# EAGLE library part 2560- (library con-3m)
3M (TM) Pak 100 4-Wall Header Source: 3M
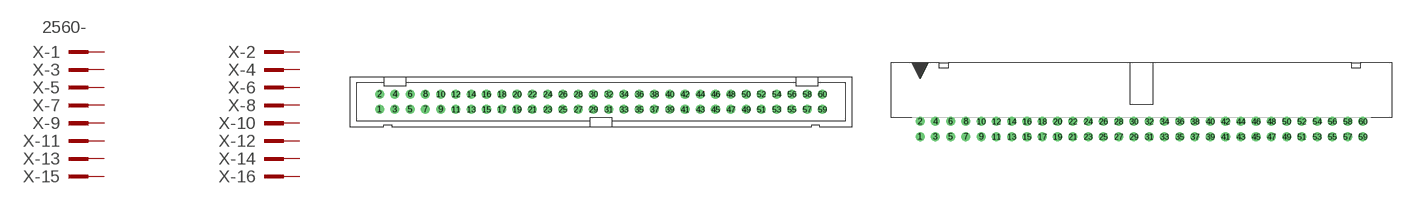
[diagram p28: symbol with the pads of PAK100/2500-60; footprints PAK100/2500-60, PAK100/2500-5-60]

Designator prefix X; gates -1=PINV -2=PIN -3=PIN -4=PIN -5=PIN -6=PIN -7=PIN -8=PIN -9=PIN -10=PIN -11=PIN -12=PIN -13=PIN -14=PIN -15=PIN -16=PIN -17=PIN -18=PIN -19=PIN -20=PIN -21=PIN -22=PIN -23=PIN -24=PIN -25=PIN -26=PIN -27=PIN -28=PIN -29=PIN -30=PIN -31=PIN -32=PIN -33=PIN -34=PIN -35=PIN -36=PIN -37=PIN -38=PIN -39=PIN -40=PIN -41=PIN -42=PIN -43=PIN -44=PIN -45=PIN -46=PIN -47=PIN -48=PIN -49=PIN -50=PIN -51=PIN -52=PIN -53=PIN -54=PIN -55=PIN -56=PIN -57=PIN -58=PIN -59=PIN -60=PIN

## 2560- (OC_FARNELL: unknown; OC_NEWARK: unknown)  [PAK100/2500-60]
1  -1:KL  pas
2  -2:KL  pas
3  -3:KL  pas
4  -4:KL  pas
5  -5:KL  pas
6  -6:KL  pas
7  -7:KL  pas
8  -8:KL  pas
9  -9:KL  pas
10  -10:KL  pas
11  -11:KL  pas
12  -12:KL  pas
13  -13:KL  pas
14  -14:KL  pas
15  -15:KL  pas
16  -16:KL  pas
17  -17:KL  pas
18  -18:KL  pas
19  -19:KL  pas
20  -20:KL  pas
21  -21:KL  pas
22  -22:KL  pas
23  -23:KL  pas
24  -24:KL  pas
25  -25:KL  pas
26  -26:KL  pas
27  -27:KL  pas
28  -28:KL  pas
29  -29:KL  pas
30  -30:KL  pas
31  -31:KL  pas
32  -32:KL  pas
33  -33:KL  pas
34  -34:KL  pas
35  -35:KL  pas
36  -36:KL  pas
37  -37:KL  pas
38  -38:KL  pas
39  -39:KL  pas
40  -40:KL  pas
41  -41:KL  pas
42  -42:KL  pas
43  -43:KL  pas
44  -44:KL  pas
45  -45:KL  pas
46  -46:KL  pas
47  -47:KL  pas
48  -48:KL  pas
49  -49:KL  pas
50  -50:KL  pas
51  -51:KL  pas
52  -52:KL  pas
53  -53:KL  pas
54  -54:KL  pas
55  -55:KL  pas
56  -56:KL  pas
57  -57:KL  pas
58  -58:KL  pas
59  -59:KL  pas
60  -60:KL  pas

## 2560-5 (OC_FARNELL: unknown; OC_NEWARK: unknown)  [PAK100/2500-5-60]
Pads as for PAK100/2500-60

## Footprint PAK100/2500-60 (pad centres in mm)
3M (TM) Pak 100 4-Wall Header Straight Source: 3M
drill 1 pad 1.422 round: 1 -36.83,-1.27; 2 -36.83,1.27; 3 -34.29,-1.27; 4 -34.29,1.27; 5 -31.75,-1.27; 6 -31.75,1.27; 7 -29.21,-1.27; 8 -29.21,1.27; 9 -26.67,-1.27; 10 -26.67,1.27; 11 -24.13,-1.27; 12 -24.13,1.27; 13 -21.59,-1.27; 14 -21.59,1.27; 15 -19.05,-1.27; 16 -19.05,1.27; 17 -16.51,-1.27; 18 -16.51,1.27; 19 -13.97,-1.27; 20 -13.97,1.27; 21 -11.43,-1.27; 22 -11.43,1.27; 23 -8.89,-1.27; 24 -8.89,1.27; 25 -6.35,-1.27; 26 -6.35,1.27; 27 -3.81,-1.27; 28 -3.81,1.27; 29 -1.27,-1.27; 30 -1.27,1.27; 31 1.27,-1.27; 32 1.27,1.27; 33 3.81,-1.27; 34 3.81,1.27; 35 6.35,-1.27; 36 6.35,1.27; 37 8.89,-1.27; 38 8.89,1.27; 39 11.43,-1.27; 40 11.43,1.27; 41 13.97,-1.27; 42 13.97,1.27; 43 16.51,-1.27; 44 16.51,1.27; 45 19.05,-1.27; 46 19.05,1.27; 47 21.59,-1.27; 48 21.59,1.27; 49 24.13,-1.27; 50 24.13,1.27; 51 26.67,-1.27; 52 26.67,1.27; 53 29.21,-1.27; 54 29.21,1.27; 55 31.75,-1.27; 56 31.75,1.27; 57 34.29,-1.27; 58 34.29,1.27; 59 36.83,-1.27; 60 36.83,1.27

## Footprint PAK100/2500-5-60 (pad centres in mm)
3M (TM) Pak 100 4-Wall Header Right Angle Source: 3M
drill 1 pad 1.422 round: 1 -36.83,-1.27; 2 -36.83,1.27; 3 -34.29,-1.27; 4 -34.29,1.27; 5 -31.75,-1.27; 6 -31.75,1.27; 7 -29.21,-1.27; 8 -29.21,1.27; 9 -26.67,-1.27; 10 -26.67,1.27; 11 -24.13,-1.27; 12 -24.13,1.27; 13 -21.59,-1.27; 14 -21.59,1.27; 15 -19.05,-1.27; 16 -19.05,1.27; 17 -16.51,-1.27; 18 -16.51,1.27; 19 -13.97,-1.27; 20 -13.97,1.27; 21 -11.43,-1.27; 22 -11.43,1.27; 23 -8.89,-1.27; 24 -8.89,1.27; 25 -6.35,-1.27; 26 -6.35,1.27; 27 -3.81,-1.27; 28 -3.81,1.27; 29 -1.27,-1.27; 30 -1.27,1.27; 31 1.27,-1.27; 32 1.27,1.27; 33 3.81,-1.27; 34 3.81,1.27; 35 6.35,-1.27; 36 6.35,1.27; 37 8.89,-1.27; 38 8.89,1.27; 39 11.43,-1.27; 40 11.43,1.27; 41 13.97,-1.27; 42 13.97,1.27; 43 16.51,-1.27; 44 16.51,1.27; 45 19.05,-1.27; 46 19.05,1.27; 47 21.59,-1.27; 48 21.59,1.27; 49 24.13,-1.27; 50 24.13,1.27; 51 26.67,-1.27; 52 26.67,1.27; 53 29.21,-1.27; 54 29.21,1.27; 55 31.75,-1.27; 56 31.75,1.27; 57 34.29,-1.27; 58 34.29,1.27; 59 36.83,-1.27; 60 36.83,1.27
